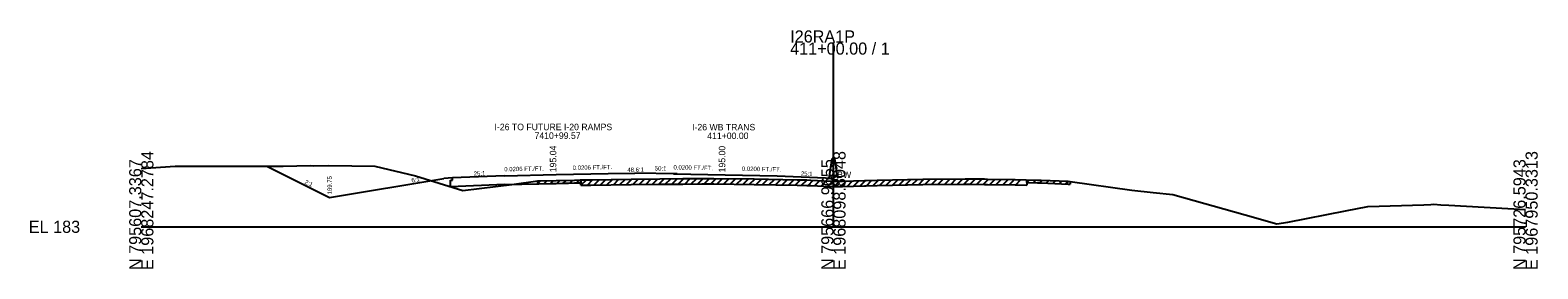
# Model space of a CAD drawing. Extents: x -44 to 4323, y -10 to 9601.
# Drawn here: x -25.7 to 322.8, y 6990.3 to 7045.4 of the extents above; entities that cross this region are included whole.
import ezdxf

# ---------------------------------------------------------------- set-up
doc = ezdxf.new("R2010")
doc.units = 0
for name, color, linetype in [('1', 7, 'Continuous'), ('DateStamp', 7, 'Continuous'), ('NotForConst', 7, 'Continuous'), ('QCQA', 7, 'Continuous'), ('RD_SHT_Bndy', 7, 'Continuous'), ('RD_SHT_Iplotshp', 7, 'Continuous'), ('RD_SHT_TX', 7, 'Continuous'), ('RD_XS_ExGround', 7, 'Continuous'), ('RD_XS_Misc_Line', 7, 'Continuous'), ('RD_XS_Pave', 7, 'Continuous'), ('RD_XS_PaveShd', 7, 'Continuous'), ('RD_XS_TX_Elev_PR', 7, 'Continuous'), ('RD_XS_TX_Profile', 7, 'Continuous'), ('RD_XS_TX_ShdSlope', 7, 'Continuous'), ('RD_XS_TX_Slope', 7, 'Continuous'), ('seal', 7, 'Continuous'), ('TR SN EXTRUDED PANEL SIGNS - GROUND MOUNTED', 7, 'Continuous')]:
    doc.layers.add(name, color=color, linetype=linetype)

msp = doc.modelspace()

# ---------------------------------------------------------------- linework, layer by layer
at = {"layer": 'DateStamp'}
msp.add_lwpolyline([(0, 7013.42), (7.85, 7013.97), (32.83, 7014.01), (39.12, 7014.14), (39.74, 7014.06), (43.38, 7014.18), (53.96, 7013.98), (63.41, 7011.78), (74.32, 7008.34), (85.69, 7009.77), (91.63, 7010.58), (100.13, 7010.8), (101.43, 7010.83), (103.94, 7010.87), (113.21, 7011.02), (119.9, 7011.07), (125.19, 7011.11), (129.56, 7011.16), (130.47, 7011.17), (132.33, 7011.16), (141.66, 7011.05), (151.65, 7010.85), (153.84, 7010.81), (154.81, 7010.76), (159.36, 7010.54), (160, 7010.54), (161.65, 7010.53), (162.13, 7010.52), (167.16, 7010.7), (167.58, 7010.71), (170.14, 7010.76), (180.64, 7010.98), (190.42, 7011.07), (191.72, 7011.08), (194.92, 7011.05), (195.59, 7011.03), (202.01, 7010.92), (207.18, 7010.76), (208.05, 7010.74), (214.24, 7010.5), (214.72, 7010.48), (228.98, 7008.45), (233.91, 7007.88), (238.46, 7007.43), (255.18, 7002.75), (262.47, 7000.66), (265.03, 7001.06), (278.37, 7003.67), (283.5, 7004.67), (296.49, 7005.08), (298.13, 7005.16), (298.8, 7005.19), (300.39, 7005.05), (302.3, 7004.97), (320, 7003.96)], dxfattribs=at)
at = {"layer": 'NotForConst'}
for p, q in [((91.63, 7009.95), (92.27, 7010.59)), ((93.13, 7009.99), (93.77, 7010.63)), ((94.63, 7010.03), (95.27, 7010.67)), ((96.13, 7010.07), (96.77, 7010.71)), ((97.63, 7010.11), (98.27, 7010.75)), ((99.13, 7010.14), (99.77, 7010.79)), ((100.63, 7010.18), (101.27, 7010.82)), ((101.63, 7009.58), (102.9, 7010.85)), ((103.13, 7009.61), (104.4, 7010.88)), ((104.63, 7009.63), (105.9, 7010.9)), ((106.13, 7009.65), (107.4, 7010.92)), ((107.63, 7009.68), (108.9, 7010.95)), ((109.13, 7009.7), (110.4, 7010.97)), ((110.63, 7009.73), (111.9, 7011)), ((112.13, 7009.75), (113.4, 7011.02)), ((113.63, 7009.77), (114.89, 7011.03)), ((115.13, 7009.78), (116.39, 7011.04)), ((116.63, 7009.79), (117.89, 7011.05)), ((118.13, 7009.8), (119.39, 7011.06)), ((119.63, 7009.82), (120.89, 7011.07)), ((121.13, 7009.83), (122.39, 7011.09)), ((122.63, 7009.84), (123.89, 7011.1)), ((124.13, 7009.85), (125.39, 7011.11)), ((125.63, 7009.86), (126.9, 7011.13)), ((127.13, 7009.88), (128.4, 7011.15)), ((128.63, 7009.9), (129.9, 7011.17)), ((130.13, 7009.92), (131.38, 7011.16)), ((131.63, 7009.91), (132.87, 7011.15)), ((133.13, 7009.9), (134.37, 7011.13)), ((134.63, 7009.88), (135.87, 7011.12)), ((136.13, 7009.86), (137.37, 7011.1)), ((137.63, 7009.84), (138.87, 7011.08)), ((139.13, 7009.83), (140.37, 7011.06)), ((140.63, 7009.81), (141.87, 7011.04)), ((142.13, 7009.79), (143.36, 7011.01)), ((143.63, 7009.76), (144.86, 7010.98)), ((145.13, 7009.73), (146.36, 7010.95)), ((146.63, 7009.7), (147.86, 7010.92)), ((148.13, 7009.67), (149.36, 7010.9)), ((149.63, 7009.64), (150.86, 7010.87)), ((151.13, 7009.61), (152.36, 7010.84)), ((152.63, 7009.58), (153.86, 7010.8)), ((154.13, 7009.54), (155.33, 7010.73)), ((155.63, 7009.47), (156.83, 7010.66)), ((157.13, 7009.4), (158.33, 7010.59)), ((158.64, 7009.33), (159.85, 7010.54)), ((160.14, 7009.29), (161.38, 7010.53)), ((161.64, 7009.28), (162.91, 7010.55)), ((163.14, 7009.31), (164.43, 7010.6)), ((164.64, 7009.36), (165.93, 7010.65)), ((166.14, 7009.41), (167.43, 7010.7)), ((167.64, 7009.46), (168.91, 7010.74)), ((169.14, 7009.49), (170.41, 7010.77)), ((170.64, 7009.52), (171.91, 7010.8)), ((172.14, 7009.55), (173.41, 7010.83)), ((173.64, 7009.58), (174.91, 7010.86)), ((175.14, 7009.61), (176.41, 7010.89)), ((176.64, 7009.65), (177.91, 7010.92)), ((178.14, 7009.68), (179.41, 7010.95)), ((179.64, 7009.71), (180.91, 7010.98)), ((181.14, 7009.73), (182.4, 7010.99)), ((182.64, 7009.75), (183.9, 7011.01)), ((184.14, 7009.76), (185.4, 7011.02)), ((185.64, 7009.77), (186.9, 7011.03)), ((187.14, 7009.79), (188.4, 7011.05)), ((188.64, 7009.8), (189.9, 7011.06)), ((190.14, 7009.81), (191.4, 7011.07)), ((191.64, 7009.83), (192.88, 7011.07)), ((193.14, 7009.81), (194.38, 7011.05)), ((194.64, 7009.8), (195.87, 7011.03)), ((196.14, 7009.77), (197.37, 7011)), ((197.64, 7009.75), (198.87, 7010.98)), ((199.14, 7009.72), (200.37, 7010.95)), ((200.64, 7009.7), (201.87, 7010.93)), ((202.14, 7009.67), (203.35, 7010.88)), ((204.71, 7010.21), (205.31, 7010.82)), ((206.21, 7010.17), (206.81, 7010.77)), ((207.71, 7010.12), (208.31, 7010.73)), ((209.21, 7010.07), (209.81, 7010.67)), ((210.71, 7010.01), (211.31, 7010.61)), ((212.21, 7009.95), (212.81, 7010.55)), ((213.71, 7009.89), (214.31, 7010.49))]:
    msp.add_line(p, q, dxfattribs=at)
at = {"layer": 'QCQA'}
for p, q in [((101.63, 7010.83), (103.94, 7010.87)), ((101.63, 7010.83), (101.63, 7010.12)), ((103.94, 7010.87), (113.21, 7011.02)), ((113.21, 7011.02), (119.9, 7011.07)), ((119.9, 7011.07), (125.19, 7011.11)), ((125.19, 7011.11), (129.56, 7011.16)), ((129.56, 7011.16), (130.47, 7011.17)), ((130.47, 7011.17), (132.33, 7011.16)), ((132.33, 7011.16), (141.66, 7011.05)), ((141.66, 7011.05), (151.65, 7010.85)), ((151.65, 7010.85), (153.84, 7010.81)), ((153.84, 7010.81), (154.81, 7010.76)), ((154.81, 7010.76), (159.36, 7010.54)), ((159.36, 7010.54), (160, 7010.54))]:
    msp.add_line(p, q, dxfattribs=at)
at = {"layer": 'RD_SHT_Bndy'}
for p, q in [((160, 7000), (160, 7042.53)), ((0, 7000), (160, 7000)), ((160, 7000), (320, 7000))]:
    msp.add_line(p, q, dxfattribs=at)
at = {"layer": 'RD_SHT_Iplotshp'}
for p, q in [((91.63, 7009.95), (91.63, 7010.58)), ((91.63, 7009.95), (100.13, 7010.17)), ((100.13, 7010.17), (101.43, 7010.2)), ((101.43, 7010.2), (101.63, 7010.21)), ((101.63, 7009.58), (101.63, 7010.83)), ((101.63, 7010.83), (101.63, 7010.21)), ((101.63, 7009.58), (103.94, 7009.62)), ((103.94, 7009.62), (113.21, 7009.77)), ((113.21, 7009.77), (119.9, 7009.82)), ((119.9, 7009.82), (125.19, 7009.86)), ((125.19, 7009.86), (129.56, 7009.91)), ((129.56, 7009.91), (130.47, 7009.92)), ((130.47, 7009.92), (132.33, 7009.91)), ((132.33, 7009.91), (141.66, 7009.8)), ((141.66, 7009.8), (151.65, 7009.6)), ((151.65, 7009.6), (153.84, 7009.56)), ((153.84, 7009.56), (154.81, 7009.51)), ((154.81, 7009.51), (159.36, 7009.29)), ((159.36, 7009.29), (160, 7009.29)), ((160, 7009.29), (161.65, 7009.28)), ((161.65, 7009.28), (162.13, 7009.27)), ((162.13, 7009.27), (167.16, 7009.45)), ((167.16, 7009.45), (167.58, 7009.46)), ((167.58, 7009.46), (170.14, 7009.51)), ((170.14, 7009.51), (180.64, 7009.73)), ((180.64, 7009.73), (190.42, 7009.82)), ((190.42, 7009.82), (191.72, 7009.83)), ((191.72, 7009.83), (194.92, 7009.8)), ((194.92, 7009.8), (195.59, 7009.78)), ((195.59, 7009.78), (202.01, 7009.67)), ((202.01, 7009.67), (204.71, 7009.59)), ((204.71, 7010.84), (204.71, 7009.59)), ((204.71, 7010.21), (204.71, 7010.84)), ((204.71, 7010.21), (207.18, 7010.14)), ((207.18, 7010.14), (208.05, 7010.11)), ((208.05, 7010.11), (214.24, 7009.87)), ((214.24, 7009.87), (214.72, 7009.85)), ((214.72, 7010.48), (214.72, 7009.85))]:
    msp.add_line(p, q, dxfattribs=at)
at = {"layer": 'RD_XS_Misc_Line'}
for p, q in [((71.44, 7010.73), (71.94, 7010.75)), ((71.44, 7009.25), (71.44, 7010.73)), ((83.94, 7009.75), (71.44, 7009.25)), ((71.94, 7010.75), (71.94, 7011.31)), ((83.94, 7009.75), (95.94, 7010)), ((95.94, 7010), (101.63, 7010.12))]:
    msp.add_line(p, q, dxfattribs=at)
at = {"layer": 'RD_XS_Pave'}
for p, q in [((29.03, 7014), (43.54, 7006.75)), ((43.54, 7006.75), (69.94, 7011.15))]:
    msp.add_line(p, q, dxfattribs=at)
at = {"layer": 'RD_XS_PaveShd'}
msp.add_line((71.94, 7011.31), (69.94, 7011.15), dxfattribs=at)
at = {"layer": 'RD_XS_TX_Elev_PR'}
for p, q in [((83.94, 7011.79), (71.94, 7011.31)), ((107.95, 7012.29), (114.1, 7012.41)), ((123.84, 7012.22), (114.1, 7012.41)), ((147, 7011.76), (160, 7011.24)), ((160, 7011.24), (160, 7010.54))]:
    msp.add_line(p, q, dxfattribs=at)
at = {"layer": 'RD_XS_TX_ShdSlope'}
for p, q in [((159, 7011.26), (159.67, 7015.74)), ((160, 7015.74), (159.67, 7015.74)), ((160, 7015.74), (160.33, 7015.74)), ((161, 7011.26), (160.33, 7015.74))]:
    msp.add_line(p, q, dxfattribs=at)
at = {"layer": 'RD_XS_TX_Slope'}
for p, q in [((83.94, 7011.79), (95.94, 7012.04)), ((95.94, 7012.04), (107.95, 7012.29)), ((123, 7012.24), (135, 7012)), ((135, 7012), (147, 7011.76))]:
    msp.add_line(p, q, dxfattribs=at)

# ---------------------------------------------------------------- texts
at = {"layer": '1'}
for s, p in [('I-26 TO FUTURE I-20 RAMPS', (81.66, 7022.29)), ('I-26 WB TRANS', (127.33, 7022.25)), ('7410+99.57', (90.9, 7020.29)), ('411+00.00', (130.83, 7020.25))]:
    msp.add_text(s, height=1.5, dxfattribs=at).set_placement(p)
at = {"layer": 'RD_SHT_Bndy'}
for s, p in [('I26RA1P', (150, 7042.53)), ('411+00.00 / 1', (150, 7039.73)), ('EL 183', (-26, 6998.6))]:
    msp.add_text(s, height=2.8, dxfattribs=at).set_placement(p)
for s, p in [('E 1968247.2784', (2.8, 6990)), ('E 1968098.8048', (162.8, 6990)), ('E 1967950.3313', (322.8, 6990)), ('N 795607.3367', (0, 6990)), ('N 795666.9655', (160, 6990)), ('N 795726.5943', (320, 6990))]:
    msp.add_text(s, height=2.8, rotation=90, dxfattribs=at).set_placement(p)
at = {"layer": 'RD_SHT_TX'}
msp.add_text('193.54', height=1, rotation=90, dxfattribs=at).set_placement((161, 7010.54))
at = {"layer": 'RD_XS_ExGround'}
for s, rotation, p in [('25:1', 2.2899, (76.87, 7011.76)), ('48.6:1', 1.1783, (112.37, 7012.63)), ('50:1', 358.8542, (118.7, 7013)), ('25:1', 357.7094, (152.46, 7011.79))]:
    msp.add_text(s, height=1, rotation=rotation, dxfattribs=at).set_placement(p)
at = {"layer": 'RD_XS_TX_Profile'}
msp.add_text('WBW', height=1.5, dxfattribs=at).set_placement((159, 7011.26))
at = {"layer": 'seal'}
for s, p in [(' 195.04', (95.94, 7012.04)), (' 195.00', (135, 7012))]:
    msp.add_text(s, height=1.5, rotation=90, dxfattribs=at).set_placement(p)
at = {"layer": 'TR SN EXTRUDED PANEL SIGNS - GROUND MOUNTED'}
for s, rotation, p in [('0.0206 FT./FT.', 1.1793, (83.92, 7012.79)), ('0.0206 FT./FT.', 1.1783, (99.73, 7013.12)), ('0.0200 FT./FT.', 358.8542, (123.02, 7013.24)), ('0.0200 FT./FT.', 358.8542, (138.83, 7012.92)), ('2:1', 333.4349, (37.64, 7010.02)), ('189.75', 90, (44.04, 7007.47)), ('6:1', 9.4623, (62.53, 7010.21))]:
    msp.add_text(s, height=1, rotation=rotation, dxfattribs=at).set_placement(p)

doc.saveas('drawing.dxf')
